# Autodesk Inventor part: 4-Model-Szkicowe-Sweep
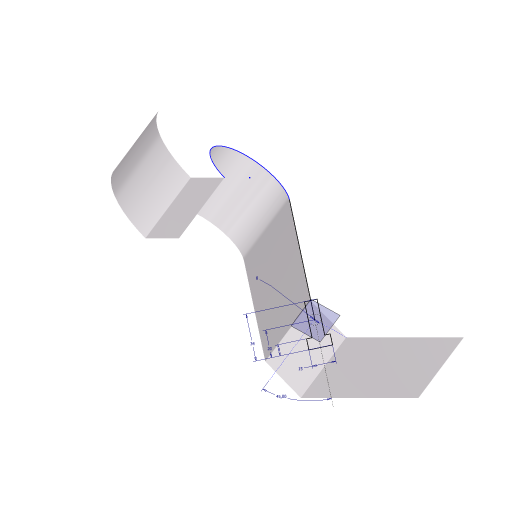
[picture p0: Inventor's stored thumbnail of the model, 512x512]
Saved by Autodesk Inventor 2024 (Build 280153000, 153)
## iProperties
Company: ATC
Created: 2023-03
Part Number: 4-Model-Szkicowe-Sweep
Document SubType Name: Modeling
Designer: Andrzej Jaskulski
Manufacturer: Standard
Standards Organization: Custom
Material: Kurs-AJ
Density: 1 g/cm^3
Mass: 879.444 g
Surface Area: 822.452 cm^2
Volume: 879.444 cm^3
Appearance: Kurs-AJ
Checked By: A.J.
Engr Approved By: Andrzej Jaskulski
Mfg Approved By: Andrzej Jaskulski
Authority: A.J.
Title: A.J.: Kurs R2024-MEP
Author: Andrzej Jaskulski
Revision Number: 1/24
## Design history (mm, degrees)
sketch "Zarys dwójki"
  geometry: L1 (0, 0)-(140, 0); L2 (140, 0)-(140, 40); L3 (140, 40)-(61.086, 40); L4 (0, 0)-(0, 34.326); L5 (0, 34.326)-(91.58, 129.16); L6 (61.086, 40)-(120.354, 101.374); L7 (40, 150)-(0, 150); A1 r 30 centre (70, 150) between (91.58, 129.16) and (40, 150); A2 r 70 centre (70, 150) between (120.354, 101.374) and (0, 150)
  constraints: 14 end point, 4 point on circle, 3 perpendicular, 2 centre point, 2 parallel, 2 tangent, 1 coincident, 1 horizontal, 1 point on line, 1 other
  dimensions: "d0" = 140 distance of L1.start L1.end; "d1" = 150 distance from line of A1.centre L1; "d2" = 70 radius of A2; "d3" = 30 radius of A1; "d4" = 70 distance from line of L4 A1.centre; "d5" = 46 deg angle of L6 L3; "d6" = 40 distance of L1.end L2.end
extrude "Dwójka" new body sketch "Zarys dwójki" distance "d7" = 50; taper "d8" = 0 deg
node "Prostopadła do Ścieżki"
sketch "Rowek"
  geometry: L1 (0, 0)-(23.845, 0) reference; L2 (23.845, -50)-(23.845, 0) reference; L3 (23.845, 0)-(-20.721, -44.566); L4 (36.573, 7.071)-(18.188, -11.314); L5 (18.188, -11.314)-(20.663, -13.789); L6 (20.663, -13.789)-(15.006, -19.445); L7 (15.006, -19.445)-(4.4, -8.839); L8 (4.4, -8.839)-(10.056, -3.182); L9 (10.056, -3.182)-(12.531, -5.657); L10 (12.531, -5.657)-(30.916, 12.728); L11 (30.916, 12.728)-(36.573, 7.071); C1 r 4 at (23.845, 0)
  constraints: 18 end point, 6 parallel, 2 equal length, 2 tangent, 1 centre point, 1 coincident, 1 collinear, 1 perpendicular
  dimensions: "d23" = 45 deg angle of L3 L2; "d24" = 8 diameter of C1; "d25" = 15 distance of L6.end L7.end; "d26" = 20 distance from line of L1.end L7; "d27" = 34 distance between parallel lines of L7 L11; "d28" = 8 distance of L5.end L6.end
sketch "Ścieżka 2D"
  geometry: L1 (91.58, 129.16)-(-17.153, 16.564); L2 (-14.275, 13.785)-(-20.03, 19.343) reference; A1 r 30 centre (70, 150) between (91.58, 129.16) and (40, 150) reference
  constraints: 2 end point, 1 midpoint, 1 tangent
node "Bryła1"
node "Korpusy bryłowe"
node "Korpusy powierzchniowe"
